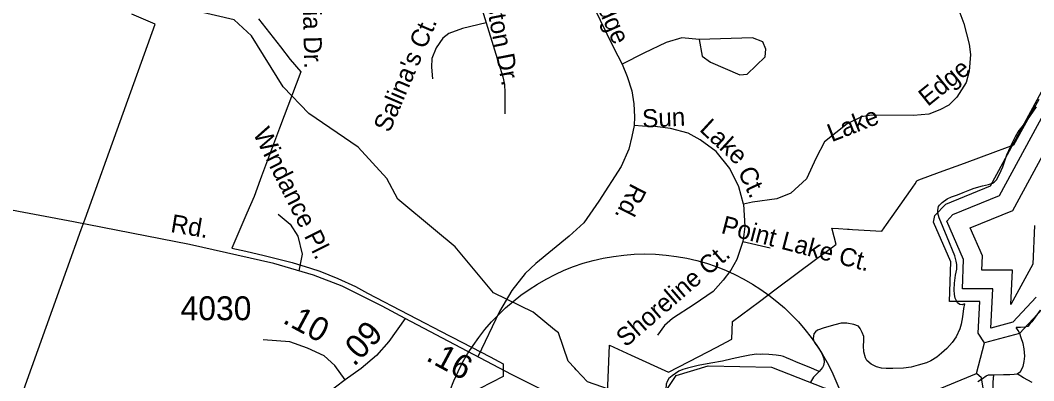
# Model space of a CAD drawing. Extents: x 2001466 to 2224147, y 644118 to 847247.
# Drawn here: x 2055654 to 2060968, y 689110 to 690998 of the extents above; entities that cross this region are included whole.
import ezdxf

# ---------------------------------------------------------------- set-up
doc = ezdxf.new("R2010")
doc.units = 0
for name, color, linetype in [('Exist Boundary Political City Limit New', 7, 'Continuous'), ('Exist Hydrographic Buffer Line', 7, 'Continuous'), ('Exist Hydrographic Creek Single Shore', 7, 'Continuous'), ('Exist Hydrographic Lake Shore', 7, 'Continuous'), ('Exist Hydrographic Misc Water Feature', 7, 'Continuous'), ('Exist Road Non-System Type 51', 7, 'Continuous'), ('Exist Road Non-System Type 51 Label', 7, 'Continuous'), ('Exist Road Primary US Ramp 1 Lane  Attributed', 7, 'Continuous'), ('Exist Road Secondary Mileage Hundredths English Label', 7, 'Continuous'), ('Exist Road Secondary Type 51 Attributed', 7, 'Continuous'), ('Exist Road Secondary Type 51 Label', 7, 'Continuous'), ('Exist Road Secondary Type 51 Number Label', 7, 'Continuous'), ('Map Preparation Boundary City Limit Buffer Line', 7, 'Continuous')]:
    doc.layers.add(name, color=color, linetype=linetype)

msp = doc.modelspace()

# ---------------------------------------------------------------- linework, layer by layer
at = {"layer": 'Exist Boundary Political City Limit New'}
for points in [[(2055638.9, 688971.2), (2055898.6, 689692.2), (2055974, 689901.7), (2055994.5, 689958.6), (2056361.4, 690977.2), (2056239, 691029.4)], [(2056902.9, 691006.4), (2057017.8, 690858.8), (2057068.6, 690793.3), (2057124.4, 690728.6), (2057014.1, 690433.4), (2056919.6, 690182.2), (2056912.8, 690163.3), (2056880.1, 690074.4), (2056842.1, 689987.1), (2056762.9, 689805), (2056836.1, 689788.6), (2056933.4, 689765.3), (2057030.9, 689741.8), (2057079.6, 689728.8), (2057175, 689700.2), (2057225.2, 689683.6), (2057319.4, 689646.1), (2057411.6, 689604.2), (2057474.2, 689569.2), (2057904.8, 689345.7), (2057918.8, 689338.4), (2058020.2, 689285.7), (2058118.2, 689234.8), (2058186.5, 689199.4), (2058185.8, 689132.1), (2057941.8, 689007)], [(2058730.8, 688997.6), (2058744, 689296.2), (2058856.9, 689244.9), (2059053.9, 689155.4), (2059213, 689237.9), (2059303.6, 689284.8), (2059386.1, 689327.5), (2059388.8, 689419.9), (2059530.4, 689525.4), (2059618.5, 689591.1), (2059831.4, 689749.6), (2059907.6, 689806.4), (2059930.2, 689823.2), (2059931.6, 689824.3), (2059911, 689903.7), (2059909.4, 689910.1), (2059944.2, 689907.8), (2059992, 689904.8), (2060000, 689904.2), (2060017.4, 689903.1), (2060171.4, 689893.4), (2060196.4, 689929), (2060246.2, 690000), (2060321.4, 690106.9), (2060345.9, 690141.8), (2060355.4, 690157.6), (2060366.6, 690161.8), (2060474.5, 690201.8), (2060605.8, 690250.4), (2060769.9, 690311.2), (2060863.6, 690346.1), (2060911.4, 690431.7), (2060996.8, 690584.5)]]:
    msp.add_lwpolyline(points, dxfattribs=at)
at = {"layer": 'Exist Hydrographic Buffer Line'}
for points in [[(2060743.8, 689385.9), (2060753.7, 689591.6), (2060594.8, 689591.6), (2060600, 689745.1), (2060512.2, 689946.2), (2060544.5, 689980.2), (2060788.3, 690079.9), (2061197.5, 690832.2)], [(2060848.3, 689510.3), (2060856.9, 689690.1), (2060696.6, 689690), (2060699.1, 689764), (2060635, 689910.9), (2060858, 690002.1), (2061295.9, 690807.2)], [(2060973, 689923.5), (2060963.8, 689720.1), (2060848.3, 689510.3)], [(2060981.4, 689547.9), (2060858, 689416.3)], [(2060858, 689416.3), (2060743.8, 689385.9)]]:
    msp.add_lwpolyline(points, dxfattribs=at)
at = {"layer": 'Exist Hydrographic Creek Single Shore'}
msp.add_lwpolyline([(2058953, 688895.2), (2059019.8, 688939.8), (2059044, 689063.9), (2059093.9, 689138.4), (2059261, 689187.5), (2059594, 689180.7), (2059869, 689073.4), (2060068.9, 689033.3), (2060426.9, 689048.9), (2060668.9, 689149)], dxfattribs=at)
at = {"layer": 'Exist Hydrographic Lake Shore'}
for points in [[(2060709.9, 689308.9), (2060676.9, 689358.8), (2060684.9, 689526), (2060527, 689525.9), (2060533.9, 689732.5), (2060442.9, 689941.1), (2060450.4, 689976.4), (2060506.6, 690035.6), (2060741.9, 690131.8), (2061131.9, 690848.9)], [(2061034.9, 689509.1), (2060893, 689357.7)], [(2060893, 689357.7), (2060709.9, 689308.9)]]:
    msp.add_lwpolyline(points, dxfattribs=at)
at = {"layer": 'Exist Hydrographic Misc Water Feature'}
for p, q in [((2060668.9, 689149), (2060709.9, 689308.9)), ((2058569.8, 689166.9), (2058561.6, 689175.5))]:
    msp.add_line(p, q, dxfattribs=at)
for points in [[(2057830.9, 689897.6), (2057633.9, 690060.5), (2057576.1, 690170), (2057426, 690333.8), (2057167, 690509.7), (2057033.1, 690650.2), (2056866, 690916), (2056774.9, 690999.9), (2056241, 691125.6), (2055633.4, 691114.4)], [(2060605.1, 689512.3), (2060593, 689508.5), (2060580.9, 689510.3), (2060568.8, 689518.7), (2060556.9, 689542.4), (2060552.6, 689562.5), (2060550.8, 689586.3), (2060552.6, 689620.5), (2060558.7, 689662.6), (2060564.5, 689694.5), (2060564.7, 689718.5), (2060562.4, 689736.2), (2060554.4, 689764.2), (2060514.3, 689862.4), (2060472, 689964.1), (2060465.9, 689988.2), (2060466.1, 690004), (2060469.8, 690022), (2060473.9, 690030.4), (2060488, 690044.4), (2060514, 690062.4), (2060537.6, 690074.2), (2060567.8, 690084.2), (2060597.9, 690096.3), (2060633.8, 690110.3), (2060655.9, 690118.3), (2060699.6, 690130.8), (2060731.6, 690138.5), (2060751.7, 690144.8), (2060761.5, 690150.6), (2060773.8, 690162.5), (2060789.4, 690192.6), (2060805.6, 690230.7), (2060827.4, 690292.7), (2060859.1, 690360.9), (2060873.1, 690388.8), (2060887, 690413.1), (2060907.3, 690440.8), (2060935, 690477.2), (2060982.8, 690544.9)], [(2058456.2, 689377.7), (2058344, 689468.6), (2058135, 689571.3), (2057934.9, 689811.6), (2057830.9, 689897.6)], [(2060605.1, 689512.3), (2060600.8, 689488.7), (2060595, 689444.5), (2060587, 689406.4), (2060581.3, 689382.5), (2060561.2, 689340.6), (2060541.1, 689310.3), (2060513.4, 689278.4), (2060485.5, 689254.3), (2060459.7, 689234.2), (2060429.6, 689214.1), (2060405.4, 689204.4), (2060361.7, 689192.3), (2060325.6, 689182), (2060285.4, 689175.9), (2060229.4, 689173.8), (2060193.8, 689174), (2060169.4, 689175.6), (2060143.5, 689183.6), (2060115.6, 689197.6), (2060093.5, 689215.5), (2060085.7, 689229.7), (2060077.5, 689261.8), (2060075.2, 689293.8), (2060077.3, 689319.4), (2060077.3, 689341.7), (2060068.9, 689363.7), (2060059, 689383.4), (2060049.2, 689395.5), (2060025.4, 689405.6), (2059988.9, 689411.5), (2059959.2, 689411.5), (2059925.1, 689403.3), (2059869.2, 689387.1), (2059834.9, 689375.2), (2059823.4, 689367.2), (2059815, 689355.1), (2059811.5, 689330.9), (2059815, 689317), (2059821.6, 689305), (2059841.5, 689279.3), (2059857.7, 689253.3), (2059867.7, 689227.1), (2059869.6, 689207.3), (2059865.7, 689189.2), (2059861.4, 689179.3), (2059843.5, 689159.3)], [(2061002.9, 689479.2), (2060959, 689419.3), (2060944.7, 689403.3), (2060937.1, 689395.1), (2060921.1, 689391.1), (2060899.1, 689389.1), (2060877, 689389.2)], [(2060881.7, 689147.1), (2060899.3, 689159.1), (2060913.5, 689185.3), (2060919, 689211.2), (2060921.3, 689239.3), (2060919, 689277.3), (2060913.1, 689305), (2060903.2, 689334.9), (2060895, 689357.3), (2060887, 689373.1), (2060877, 689389.2)], [(2058561.6, 689175.5), (2058526.9, 689212.2), (2058476.9, 689361), (2058456.2, 689377.7)], [(2059533.3, 689248.5), (2059513.8, 689248.7), (2059479.6, 689244.5), (2059435.5, 689234.6), (2059387.3, 689224.4), (2059335.6, 689212), (2059275.7, 689202), (2059207.9, 689190), (2059153.5, 689175.9), (2059127.9, 689169.7), (2059108, 689159.7), (2059071.7, 689135.6), (2059055.7, 689121.8), (2059045.7, 689105.5), (2059040.1, 689091.7), (2059039.9, 689065.8), (2059044, 689033.5), (2059047.9, 689003.8), (2059048.3, 688985.8), (2059046.3, 688965.9), (2059042.4, 688949.8), (2059036, 688937.8), (2059028, 688925.6), (2059010.6, 688909.6)], [(2059843.5, 689159.3), (2059791.6, 689181), (2059733.4, 689204.8), (2059693.6, 689221), (2059671.5, 689230.9), (2059655.5, 689236.9), (2059641.8, 689240.6), (2059617.8, 689244.7), (2059579.8, 689246.8), (2059545.6, 689248.7), (2059533.3, 689248.5)], [(2058953, 688895.2), (2058777.9, 689053), (2058628, 689105.3), (2058569.8, 689166.9)], [(2059843.5, 689159.3), (2059813.6, 689129), (2059797.6, 689103)], [(2061723.1, 685974.1), (2061047.8, 686743), (2060930.9, 687066.9), (2060913.9, 687316.5), (2060779.8, 687657.2), (2060746, 687799), (2060762, 688274.4), (2060820, 688476.6), (2060795, 688674), (2060743.9, 688825.9), (2060693.9, 689125.6), (2060668.9, 689149)], [(2060675.6, 689106.6), (2060699.6, 689122.8), (2060719.7, 689136.8), (2060731.4, 689140.7), (2060757.4, 689140.8)], [(2060757.4, 689140.8), (2060753.5, 689102.9), (2060753.5, 689074.9), (2060755.4, 689053.1), (2060759.7, 689033), (2060765.4, 689011), (2060773.8, 688985), (2060783.7, 688949.1), (2060793.9, 688909), (2060807.7, 688869.2), (2060820, 688823.1), (2060830.2, 688787.1), (2060844.2, 688739.1), (2060858.1, 688695.2), (2060870.6, 688655.2), (2060874.3, 688621.4), (2060874.5, 688587.2), (2060872.7, 688547.4), (2060870.4, 688519.3), (2060868.8, 688511.1)], [(2060757.4, 689140.8), (2060809.1, 689143.1), (2060843.2, 689143.2), (2060865.5, 689145.1), (2060881.7, 689147.1)], [(2060959.4, 689101.3), (2060937.7, 689113.1), (2060915.3, 689125), (2060881.7, 689147.1)]]:
    msp.add_lwpolyline(points, dxfattribs=at)
at = {"layer": 'Exist Road Non-System Type 51'}
for points in [[(2058173.8, 691595.8), (2058100.2, 691527.1), (2058056.1, 691430.8), (2058037.4, 691337.2), (2058025.4, 691250.3), (2058029.4, 691219.5), (2058040.1, 691173), (2058097.6, 690984.5)], [(2058498.5, 691449.5), (2058567.4, 691262.3), (2058587.5, 691219.5), (2058765.2, 690856.1), (2058810.7, 690767.9)], [(2060565.1, 691079.7), (2060601.7, 690982.1), (2060629.8, 690873.8), (2060636.4, 690818.9), (2060629.8, 690732), (2060613.7, 690671.8), (2060565.6, 690596.2), (2060522.8, 690553.4), (2060476.1, 690529.3), (2060418.6, 690506.6), (2060337.1, 690498.6), (2060117.9, 690501.2), (2060065.8, 690491.9), (2059989.6, 690455.8), (2059872, 690360.8), (2059828.2, 690277.7), (2059777.4, 690168), (2059694.6, 690091.8), (2059621.1, 690063.7), (2059494.1, 690045), (2059447.3, 690034.3)], [(2058097.6, 690984.5), (2057972.5, 690955.1), (2057901.7, 690928.3), (2057869.6, 690904.2), (2057834.8, 690853.4), (2057812.1, 690798.6), (2057810.8, 690753.1), (2057814.8, 690691.4)], [(2058097.6, 690984.5), (2058183.6, 690702.1), (2058193, 690662), (2058195.7, 690619.2), (2058195.7, 690508.2)], [(2059214.1, 690897.6), (2059123.7, 690905.4), (2059041, 690881.8), (2058923, 690826.7), (2058810.7, 690767.9)], [(2059214.1, 690897.6), (2059229.9, 690811), (2059273.2, 690779.5), (2059426.6, 690712.5), (2059465.9, 690716.5), (2059560.4, 690807), (2059564.3, 690846.4), (2059548.5, 690885.8), (2059493.5, 690905.4), (2059214.1, 690897.6)], [(2058810.7, 690767.9), (2058836.3, 690704.2), (2058861.7, 690628), (2058871.1, 690559.8), (2058875.1, 690491.6), (2058872.7, 690446.4)], [(2058872.7, 690446.4), (2058861.7, 690389.4), (2058844.3, 690323.9), (2058804.3, 690233), (2058688, 690051.1), (2058609.1, 689937.5), (2058531.6, 689867.9), (2058357.9, 689723.5), (2058301.8, 689671.9), (2058230.9, 689582.3), (2058166.8, 689472.7), (2058053.3, 689235.1)], [(2059447.3, 690034.3), (2059421.9, 690125.5), (2059375.2, 690221.8), (2059303, 690311.3), (2059218.8, 690371.5), (2059156, 690407.6), (2059063.8, 690431.7), (2058980.9, 690442.4), (2058916.8, 690443.7), (2058872.7, 690446.4)], [(2059447.3, 690034.3), (2059452.7, 689918), (2059448.7, 689876.5), (2059443.3, 689839.1)], [(2057007, 689981.9), (2057070, 689930.7), (2057109.3, 689867.7), (2057132.9, 689773.2), (2057115.4, 689685.6)], [(2059443.3, 689839.1), (2059411.2, 689745.5), (2059379.2, 689689.3), (2059340.4, 689637.2), (2059287, 689577), (2059188.1, 689508.8), (2059074.5, 689436.6), (2059033, 689399.1), (2058995.6, 689349.7)], [(2059443.3, 689839.1), (2059586.3, 689807)]]:
    msp.add_lwpolyline(points, dxfattribs=at)
at = {"layer": 'Exist Road Primary US Ramp 1 Lane  Attributed'}
msp.add_circle((2058929.6, 688686.9), 1087.2, dxfattribs=at)
at = {"layer": 'Exist Road Secondary Type 51 Attributed'}
for points in [[(2057671.9, 689435.8), (2057551.9, 689500.6), (2057342.1, 689604.8), (2057192.2, 689663.2), (2056983.9, 689724), (2056542.1, 689823.5), (2055933, 689942.7), (2055551.2, 690013.7), (2055282.9, 690075.3), (2055011.5, 690174), (2054790.6, 690270.3), (2054579.2, 690387.2), (2054143.7, 690672.2), (2053965.4, 690808), (2053848.6, 690901.1), (2053750.8, 691005.3), (2053676.6, 691103.2), (2053471.5, 691391.4), (2053272.7, 691686.7), (2052919.2, 692202.2), (2052770.9, 692431.2), (2052668.3, 692566.2)], [(2057671.9, 689435.8), (2057586.6, 689315.8), (2057522, 689243.2), (2057441.5, 689173.7), (2057357.8, 689115.3)], [(2058843, 688772.7), (2058812.3, 688802.4), (2058730.2, 688871.8), (2058573.7, 688971.8), (2058229.6, 689142.5), (2057834.4, 689350.1), (2057671.9, 689435.8)], [(2057357.8, 689115.3), (2057304.2, 689189.5), (2057247.4, 689240), (2057160.6, 689281.1), (2057067.5, 689314.2), (2056927.1, 689325.3)], [(2057357.8, 689115.3), (2057205.6, 688999.6), (2057078.6, 688885.2), (2056988.6, 688809), (2056897.1, 688749.8)]]:
    msp.add_lwpolyline(points, dxfattribs=at)
at = {"layer": 'Map Preparation Boundary City Limit Buffer Line'}
for points in [[(2055638.9, 688971.2), (2055898.6, 689692.2), (2055974, 689901.7), (2055994.5, 689958.6), (2056361.4, 690977.2), (2056239, 691029.4)], [(2056902.9, 691006.4), (2057017.8, 690858.8), (2057068.6, 690793.3), (2057124.4, 690728.6), (2057014.1, 690433.4), (2056919.6, 690182.2), (2056912.8, 690163.3), (2056880.1, 690074.4), (2056842.1, 689987.1), (2056762.9, 689805), (2056836.1, 689788.6), (2056933.4, 689765.3), (2057030.9, 689741.8), (2057079.6, 689728.8), (2057175, 689700.2), (2057225.2, 689683.6), (2057319.4, 689646.1), (2057411.6, 689604.2), (2057474.2, 689569.2), (2057904.8, 689345.7), (2057918.8, 689338.4), (2058020.2, 689285.7), (2058118.2, 689234.8), (2058186.5, 689199.4), (2058185.8, 689132.1), (2057941.8, 689007)], [(2058730.8, 688997.6), (2058744, 689296.2), (2058856.9, 689244.9), (2059053.9, 689155.4), (2059213, 689237.9), (2059303.6, 689284.8), (2059386.1, 689327.5), (2059388.8, 689419.9), (2059530.4, 689525.4), (2059618.5, 689591.1), (2059831.4, 689749.6), (2059907.6, 689806.4), (2059930.2, 689823.2), (2059931.6, 689824.3), (2059911, 689903.7), (2059909.4, 689910.1), (2059944.2, 689907.8), (2059992, 689904.8), (2060000, 689904.2), (2060017.4, 689903.1), (2060171.4, 689893.4), (2060196.4, 689929), (2060246.2, 690000), (2060321.4, 690106.9), (2060345.9, 690141.8), (2060355.4, 690157.6), (2060366.6, 690161.8), (2060474.5, 690201.8), (2060605.8, 690250.4), (2060769.9, 690311.2), (2060863.6, 690346.1), (2060911.4, 690431.7), (2060996.8, 690584.5)]]:
    msp.add_lwpolyline(points, dxfattribs=at)

# ---------------------------------------------------------------- texts
at = {"layer": 'Exist Road Non-System Type 51 Label'}
for s, rotation, p in [('Kinderston Dr.', 280.9616, (2058026.3, 691446.4)), ('Sadelia Dr.', 271.4669, (2057127.8, 691371.8)), ('Ridge', 293.6449, (2058633.3, 691168.2)), ("Salina's Ct.", 66.8099, (2057590.1, 690405.1)), ('Edge', 38.8597, (2060412.7, 690543.7)), ('Sun', 2.4974, (2058916.9, 690436.1)), ('Lake', 21.4516, (2059909, 690359)), ('Windance Pl.', 296.5358, (2056872.3, 690406.9)), ('Lake', 317.3211, (2059210.8, 690421.8)), ('Ct.', 295.4025, (2059414.7, 690205.1)), ('Rd.', 243.1579, (2058857.6, 690149.8)), ('Point Lake Ct.', 345.342, (2059324.4, 689884.3)), ('Shoreline Ct.', 40.9132, (2058829.4, 689282.5))]:
    msp.add_text(s, height=95, rotation=rotation, dxfattribs=at).set_placement(p)
at = {"layer": 'Exist Road Secondary Mileage Hundredths English Label'}
for s, rotation, p in [('.10', 331.698, (2057024.3, 689416.1)), ('.09', 46.9786, (2057404.6, 689180.4)), ('.16', 331.7255, (2057775.8, 689219.7))]:
    msp.add_text(s, height=125, rotation=rotation, dxfattribs=at).set_placement(p)
at = {"layer": 'Exist Road Secondary Type 51 Label'}
msp.add_text('Rd.', height=95, rotation=350.5319, dxfattribs=at).set_placement((2056438.1, 689889.3))
at = {"layer": 'Exist Road Secondary Type 51 Number Label'}
msp.add_text('4030', height=125, dxfattribs=at).set_placement((2056494.2, 689427.3))

doc.saveas('drawing.dxf')
